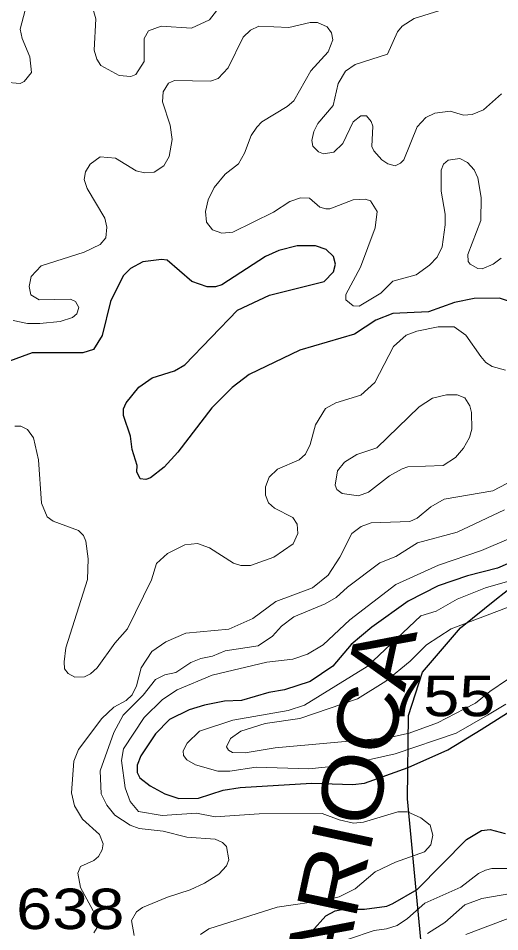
# Model space of a CAD drawing. Extents: x 577 to 602.9, y 7483.8 to 7511.6.
# Drawn here: x 583.783 to 584.735, y 7489.813 to 7491.618 of the extents above; entities that cross this region are included whole.
import ezdxf
from ezdxf.enums import TextEntityAlignment as Align

# ---------------------------------------------------------------- set-up
doc = ezdxf.new("R2010")
doc.units = 0
doc.header["$LTSCALE"] = 0.032
for name, color, linetype, lineweight in [('1', 7, 'Continuous', 25), ('2', 7, 'Continuous', 13), ('26', 7, 'Continuous', 25)]:
    doc.layers.add(name, color=color, linetype=linetype, lineweight=lineweight)
doc.layers.add('61', color=7, linetype='Continuous')

msp = doc.modelspace()

# ---------------------------------------------------------------- linework, layer by layer
at = {"layer": '1'}
for points in [[(584.6459, 7491.0564), (584.5942, 7491.0381), (584.5242, 7491.035), (584.49, 7491.0214), (584.4479, 7490.9936), (584.3397, 7490.9626), (584.2395, 7490.9141), (584.2061, 7490.8886), (584.1656, 7490.8481), (584.0988, 7490.7606), (584.0718, 7490.7312), (584.0447, 7490.7097), (584.0352, 7490.7066), (584.024, 7490.7081), (584.0177, 7490.7217), (584.0185, 7490.7344), (584.0081, 7490.7662), (584.005, 7490.7924), (583.9914, 7490.833), (583.9914, 7490.8465), (583.9962, 7490.8584), (584.0217, 7490.8894), (584.0479, 7490.9077), (584.0924, 7490.9212), (584.1123, 7490.9332), (584.2165, 7491.0413), (584.2801, 7491.0707), (584.3882, 7491.0978), (584.4065, 7491.1169), (584.4105, 7491.132), (584.4065, 7491.1471), (584.3922, 7491.1614), (584.3707, 7491.1685), (584.335, 7491.1685), (584.2984, 7491.159), (584.2721, 7491.1471), (584.1855, 7491.0914), (584.1735, 7491.0874), (584.1568, 7491.0874), (584.1266, 7491.0978), (584.0773, 7491.1399), (584.0662, 7491.1415), (584.0296, 7491.1367), (584.005, 7491.124), (583.9906, 7491.1089), (583.9652, 7491.0588), (583.9493, 7490.9912), (583.9318, 7490.9634), (583.9111, 7490.957), (583.8109, 7490.957), (583.7585, 7490.9379)], [(584.7795, 7491.0501), (584.7349, 7491.0652), (584.6848, 7491.0644), (584.6459, 7491.0564)], [(584.7707, 7490.5483), (584.731, 7490.5316), (584.6713, 7490.5165), (584.6133, 7490.4966), (584.5544, 7490.4664), (584.4821, 7490.4147), (584.4415, 7490.3805), (584.4049, 7490.3376), (584.3604, 7490.3074), (584.3095, 7490.2907), (584.2785, 7490.2859), (584.2244, 7490.27), (584.191, 7490.2684), (584.1513, 7490.2605), (584.1211, 7490.2517), (584.0821, 7490.2326), (584.0543, 7490.204), (584.0256, 7490.1603), (584.0185, 7490.142), (584.0185, 7490.1277), (584.0233, 7490.1173), (584.0439, 7490.1014), (584.0733, 7490.0855), (584.1004, 7490.076), (584.1393, 7490.0768), (584.1886, 7490.0927), (584.222, 7490.0982), (584.3628, 7490.1062), (584.4447, 7490.1038), (584.4678, 7490.1062), (584.5544, 7490.1372), (584.6324, 7490.1722), (584.6987, 7490.2126), (584.7829, 7490.2662)], [(584.3628, 7489.8128), (584.3914, 7489.8446), (584.4097, 7489.8541), (584.4264, 7489.8573), (584.4678, 7489.8573), (584.5123, 7489.8637), (584.5242, 7489.8684), (584.5719, 7489.8963), (584.6697, 7489.9949), (584.6992, 7490.0132), (584.7166, 7490.0147), (584.7461, 7490.0068)]]:
    msp.add_lwpolyline(points, dxfattribs=at)
at = {"layer": '2'}
for points in [[(583.7561, 7491.4922), (583.7871, 7491.489), (583.795, 7491.493), (583.8093, 7491.5113), (583.8062, 7491.5423), (583.7911, 7491.5781), (583.7871, 7491.5964), (583.807, 7491.6751)], [(583.9302, 7491.6401), (583.9366, 7491.617), (583.9334, 7491.555), (583.9382, 7491.5375), (583.9461, 7491.5248), (583.9827, 7491.5049), (584.0058, 7491.5033), (584.0153, 7491.5073), (584.032, 7491.5327), (584.032, 7491.5781), (584.0407, 7491.5932), (584.0654, 7491.6027), (584.1258, 7491.5987), (584.1616, 7491.6154), (584.1863, 7491.6472)], [(584.6149, 7491.6329), (584.5664, 7491.6178), (584.5425, 7491.6027), (584.533, 7491.5916), (584.5131, 7491.5471), (584.4495, 7491.5272), (584.4304, 7491.5137), (584.4161, 7491.489), (584.4057, 7491.4461), (584.3755, 7491.4103), (584.3676, 7491.3944), (584.3636, 7491.3769), (584.366, 7491.3658), (584.3771, 7491.3546), (584.3866, 7491.3506)], [(584.3994, 7491.2417), (584.3914, 7491.2417), (584.3795, 7491.2449), (584.3588, 7491.2624), (584.3413, 7491.2632), (584.3199, 7491.256), (584.288, 7491.2353), (584.2077, 7491.1956), (584.1855, 7491.1932), (584.1672, 7491.2004), (584.1552, 7491.2155), (584.1537, 7491.2361), (584.1584, 7491.2592), (584.1704, 7491.2838), (584.1926, 7491.3101), (584.2189, 7491.3308), (584.2308, 7491.3514), (584.2435, 7491.3864), (584.2546, 7491.4031), (584.265, 7491.4135), (584.3151, 7491.4437), (584.3278, 7491.4548), (584.362, 7491.5145), (584.3962, 7491.5518), (584.4049, 7491.5757), (584.4025, 7491.5892), (584.3938, 7491.6011), (584.3747, 7491.6099), (584.3604, 7491.6099), (584.3183, 7491.6003), (584.2586, 7491.6027), (584.2427, 7491.5948), (584.2276, 7491.5812), (584.1982, 7491.52), (584.1783, 7491.4993), (584.1632, 7491.4938), (584.0924, 7491.4954), (584.0805, 7491.4898), (584.0694, 7491.4731), (584.0686, 7491.4532), (584.0837, 7491.4071), (584.0877, 7491.3785), (584.0813, 7491.3451), (584.071, 7491.3268), (584.0519, 7491.3141), (584.0328, 7491.3125), (584.0161, 7491.3165), (583.9755, 7491.3419), (583.9453, 7491.3443), (583.9254, 7491.33), (583.9159, 7491.3149), (583.9135, 7491.2998), (583.9191, 7491.2815), (583.9541, 7491.2234), (583.958, 7491.2051), (583.9565, 7491.1845), (583.9453, 7491.1709), (583.9135, 7491.1558), (583.8284, 7491.1288), (583.8086, 7491.1081), (583.8046, 7491.0882), (583.8078, 7491.0715), (583.8245, 7491.062), (583.8865, 7491.0628), (583.896, 7491.0588), (583.9032, 7491.0469), (583.8992, 7491.0342), (583.8905, 7491.027), (583.8658, 7491.0191), (583.826, 7491.0151), (583.8014, 7491.0151), (583.7728, 7491.0206)], [(584.3866, 7491.3506), (584.4073, 7491.3538), (584.4248, 7491.3705), (584.4455, 7491.4135), (584.4606, 7491.4254), (584.4717, 7491.4254), (584.4813, 7491.4143), (584.4845, 7491.4047), (584.4821, 7491.365), (584.486, 7491.3562), (584.5019, 7491.3387), (584.5139, 7491.3308), (584.5282, 7491.3268), (584.5393, 7491.3316), (584.5457, 7491.3387), (584.5719, 7491.4039), (584.5894, 7491.4222), (584.6069, 7491.431), (584.6371, 7491.4349), (584.6634, 7491.427), (584.6809, 7491.4278), (584.7031, 7491.4373), (584.7389, 7491.4691)], [(584.7381, 7491.1439), (584.7222, 7491.132), (584.7007, 7491.1232), (584.692, 7491.124), (584.6769, 7491.132), (584.6729, 7491.1375), (584.6721, 7491.1511), (584.6976, 7491.2186), (584.6984, 7491.264), (584.692, 7491.3029), (584.6848, 7491.3188), (584.6713, 7491.3332), (584.6562, 7491.3411), (584.6332, 7491.3379), (584.6244, 7491.33), (584.6196, 7491.318), (584.6196, 7491.2767), (584.6276, 7491.2314), (584.6276, 7491.2099), (584.6212, 7491.1662), (584.6117, 7491.1463), (584.5966, 7491.1304), (584.5703, 7491.1113), (584.5242, 7491.0986), (584.5004, 7491.0747), (584.4574, 7491.0493), (584.4455, 7491.0501), (584.4312, 7491.062), (584.4312, 7491.0723), (584.4598, 7491.1264), (584.4892, 7491.2043), (584.4932, 7491.2361), (584.4797, 7491.2576), (584.4693, 7491.2608), (584.4455, 7491.2592), (584.3994, 7491.2417)], [(583.776, 7490.8123), (583.7879, 7490.8123), (583.8014, 7490.8052), (583.8133, 7490.7893), (583.8229, 7490.7455), (583.8292, 7490.6596), (583.8404, 7490.6326), (583.8523, 7490.6246), (583.9024, 7490.6056), (583.9119, 7490.596), (583.9167, 7490.5849), (583.9215, 7490.5499), (583.9199, 7490.5093), (583.8769, 7490.3742), (583.8738, 7490.3463), (583.8746, 7490.3328), (583.8817, 7490.3233), (583.8952, 7490.3161), (583.9143, 7490.3169), (583.9262, 7490.3225), (583.939, 7490.3344), (583.9739, 7490.3829), (583.9994, 7490.4115), (584.0463, 7490.5086), (584.0566, 7490.5404), (584.0781, 7490.5602), (584.1123, 7490.5777), (584.1378, 7490.5801), (584.1616, 7490.5714), (584.2085, 7490.5412), (584.2236, 7490.5364), (584.2427, 7490.5364), (584.2888, 7490.5531), (584.327, 7490.5793), (584.3358, 7490.6), (584.335, 7490.6183), (584.3262, 7490.6318), (584.2896, 7490.6501), (584.2777, 7490.6604), (584.2721, 7490.6755), (584.2721, 7490.6922), (584.2793, 7490.7113), (584.296, 7490.7272), (584.3389, 7490.7455), (584.3509, 7490.7566), (584.3604, 7490.7757), (584.3707, 7490.8147), (584.3906, 7490.8473), (584.4113, 7490.8584), (584.4606, 7490.8735), (584.4884, 7490.8982), (584.525, 7490.9698), (584.5505, 7490.992), (584.5711, 7491), (584.6133, 7491.0087), (584.6451, 7491.0087), (584.6681, 7490.992), (584.6976, 7490.9499), (584.7079, 7490.9379), (584.7206, 7490.93), (584.7469, 7490.9228)], [(583.9326, 7489.8104), (583.939, 7489.8215), (583.935, 7489.847), (583.9064, 7489.9002), (583.9008, 7489.9289), (583.9064, 7489.9416), (583.9326, 7489.9535), (583.9421, 7489.9615), (583.9493, 7489.975), (583.9509, 7489.9869), (583.9437, 7490.0052), (583.9103, 7490.0354), (583.8944, 7490.0617), (583.8881, 7490.0871), (583.8928, 7490.1499), (583.9024, 7490.173), (583.9485, 7490.2342), (583.9724, 7490.2565), (583.9962, 7490.27), (584.0081, 7490.2811), (584.0169, 7490.2986), (584.0264, 7490.3344), (584.0471, 7490.367), (584.0749, 7490.3861), (584.1147, 7490.4028), (584.1998, 7490.4107), (584.2467, 7490.4322), (584.2928, 7490.4656), (584.3652, 7490.4926), (584.3962, 7490.5173), (584.4192, 7490.5531), (584.4431, 7490.6), (584.4614, 7490.6135), (584.4813, 7490.6207), (584.5576, 7490.6239), (584.5719, 7490.6302), (584.599, 7490.6525), (584.6252, 7490.6676), (584.7214, 7490.6843), (584.7492, 7490.6986)], [(584.7445, 7490.6469), (584.6514, 7490.6024), (584.5727, 7490.5817), (584.5298, 7490.5547), (584.498, 7490.542), (584.4344, 7490.4942), (584.4121, 7490.4736), (584.3898, 7490.4608), (584.3278, 7490.4354), (584.3039, 7490.4171), (584.2857, 7490.3972), (584.2578, 7490.3781), (584.1926, 7490.3678), (584.1672, 7490.3575), (584.1441, 7490.3527), (584.1242, 7490.3447), (584.0948, 7490.3249), (584.0733, 7490.3209), (584.0543, 7490.3113), (584.0304, 7490.2803), (583.9906, 7490.2406), (583.9724, 7490.2064), (583.9453, 7490.1308), (583.9469, 7490.0855), (583.958, 7490.0633), (583.9739, 7490.0434), (584.0042, 7490.0235), (584.0225, 7490.0171)], [(584.4391, 7490.429), (584.5298, 7490.499), (584.6141, 7490.5372), (584.6992, 7490.5666), (584.7532, 7490.5897)], [(584.7477, 7490.2625), (584.7111, 7490.2406), (584.6491, 7490.2056), (584.5282, 7490.1642), (584.4288, 7490.142), (584.358, 7490.1348), (584.2539, 7490.138), (584.2014, 7490.13), (584.1775, 7490.13), (584.1338, 7490.1428), (584.1163, 7490.1523), (584.1099, 7490.1611), (584.1091, 7490.1706), (584.1171, 7490.1857), (584.1417, 7490.2096), (584.2077, 7490.231), (584.3167, 7490.2501), (584.3493, 7490.2605), (584.4733, 7490.3368), (584.5791, 7490.437), (584.6093, 7490.4465), (584.6514, 7490.4704), (584.7071, 7490.4926), (584.8311, 7490.5284)], [(584.7858, 7490.3352), (584.7158, 7490.2875), (584.6876, 7490.2643), (584.6658, 7490.2533), (584.6125, 7490.2255), (584.556, 7490.2056), (584.5171, 7490.1968), (584.2912, 7490.1762), (584.2316, 7490.1666), (584.2069, 7490.1674), (584.199, 7490.1714), (584.195, 7490.1786), (584.203, 7490.1945), (584.2236, 7490.2096), (584.2713, 7490.2247), (584.3397, 7490.2342), (584.4542, 7490.2732), (584.5099, 7490.3082), (584.5584, 7490.3479), (584.5902, 7490.3797), (584.6395, 7490.4115), (584.7818, 7490.4656)], [(584.1433, 7489.8072), (584.16, 7489.8183), (584.2952, 7489.8613), (584.3946, 7489.8756), (584.4177, 7489.882), (584.4495, 7489.8979), (584.4892, 7489.9313), (584.529, 7489.9503), (584.5862, 7489.971), (584.599, 7489.9845), (584.6029, 7490.0036), (584.5974, 7490.0235), (584.5791, 7490.0378), (584.5528, 7490.0497), (584.5338, 7490.0497), (584.4662, 7490.0291), (584.4463, 7490.0275), (584.4177, 7490.0338), (584.3843, 7490.0466), (584.2594, 7490.0458), (584.1727, 7490.0402), (584.1354, 7490.0474), (584.0678, 7490.0426), (584.0209, 7490.0505), (584.0042, 7490.0704), (583.9946, 7490.0974), (583.9875, 7490.1515), (583.9914, 7490.1746), (584.032, 7490.2366), (584.0686, 7490.2716), (584.0972, 7490.2907), (584.1664, 7490.3201), (584.2745, 7490.3455), (584.3262, 7490.3519), (584.3548, 7490.3614), (584.3859, 7490.3797), (584.4391, 7490.429)], [(584.0225, 7490.0171), (584.0694, 7490.0116), (584.1163, 7489.9996), (584.1727, 7489.9957), (584.1871, 7489.9893), (584.195, 7489.9814), (584.1998, 7489.9551), (584.195, 7489.9432), (584.1799, 7489.9265), (584.1513, 7489.909), (584.1234, 7489.8955), (584.0781, 7489.8812), (584.0288, 7489.8605), (584.0169, 7489.8525), (584.0073, 7489.835), (584.0121, 7489.8056)], [(584.7628, 7489.9376), (584.7198, 7489.9376), (584.7071, 7489.9344), (584.6936, 7489.9281), (584.6586, 7489.901), (584.587, 7489.8692)], [(584.5926, 7489.8096), (584.6268, 7489.8311), (584.6665, 7489.8661), (584.6999, 7489.8788), (584.7763, 7489.8915)], [(584.587, 7489.8692), (584.5528, 7489.839), (584.5322, 7489.8255), (584.5115, 7489.8183), (584.4868, 7489.8152), (584.4359, 7489.7985)], [(584.7954, 7489.8557), (584.6681, 7489.8072)]]:
    msp.add_lwpolyline(points, dxfattribs=at)
msp.add_lwpolyline([(584.6475, 7490.7503), (584.6634, 7490.7686), (584.6753, 7490.79), (584.6801, 7490.8059), (584.6793, 7490.8393), (584.6761, 7490.8521), (584.6665, 7490.868), (584.6514, 7490.8743), (584.63, 7490.8743), (584.6021, 7490.8672), (584.5759, 7490.8505), (584.4924, 7490.7694), (584.4526, 7490.7559), (584.428, 7490.7407), (584.4145, 7490.724), (584.4097, 7490.6954), (584.4129, 7490.6867), (584.424, 7490.6787), (584.4558, 7490.6747), (584.4757, 7490.6819), (584.5171, 7490.7137), (584.5425, 7490.728), (584.5536, 7490.732), (584.6236, 7490.7344)], close=True, dxfattribs=at)
at = {"layer": '26'}
msp.add_lwpolyline([(584.623, 7489.3392), (584.5531, 7490.0753), (584.5549, 7490.24), (584.5824, 7490.326), (584.6574, 7490.4138), (584.7287, 7490.4705), (584.8202, 7490.5419), (584.9703, 7490.6206), (585.1441, 7490.7139), (585.2667, 7490.7779), (585.3523, 7490.8249), (585.3623, 7490.8353)], dxfattribs=at)

# ---------------------------------------------------------------- texts
at = {"layer": '26', "width": 1.15}
msp.add_text('SERRA DA CARIOCA', height=0.12, rotation=77.797, dxfattribs=at).set_placement((584.3789, 7489.5085), align=Align.CENTER)
at = {"layer": '61', "width": 1.2}
for s, p in [('755', (584.6197, 7490.2389)), ('638', (583.886, 7489.8181))]:
    msp.add_text(s, height=0.08, dxfattribs=at).set_placement(p, align=Align.CENTER)

doc.saveas('drawing.dxf')
